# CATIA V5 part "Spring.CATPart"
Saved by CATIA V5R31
Part number: Part1
Bounding box of the stored display mesh (mm): x -50 to 50, y -44.999 to 44.983, z -4.984 to 154.984
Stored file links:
  D:\PROJECTS\Project 2021\US EDITION\CATIA V5 6R 2021\Resources\Tutorial Files\c19_catia_v5_6r2021_tut\C19_tut_01.CATPart\Spring.CATPart
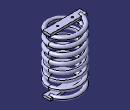
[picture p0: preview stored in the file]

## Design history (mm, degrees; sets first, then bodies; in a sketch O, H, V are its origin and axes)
Body1 (main body)
  Point1: (0, 0, 0)
  Point2: (0, 0, 150)
  Line1: type PtPt, FirstPoint Point2, SecondPoint Point1
  Point3: (40, 0, 0)
  Helix1: Direction Line1, RefPoint Point3, Pitch 20, Height 150, TaperAngle 0, Revolutions 1
  Plane1: type Normal, Curve Helix1, RefPoint vertex of Helix1, Ratio 0
  Sketch1 on Plane1, origin (0, -11.8615, 0.9439), H (1, 0, 0), V (0, 0.0793, 0.9968)
    circle A1 centre (-40, 149.5273) radius 5
    point P1 (-40, 149.5273)
    reference projected point E1 (-40, 149.5273) from vertex of Helix1
    radius A1 = 5
    coincidence: P1 E1
  Rib1: profile Sketch1, centre curve Helix1
  Sketch2 on xy-plane, origin (0, 0, 0), H (1, 0, 0), V (0, 1, 0)
    line L1 (-50, 10) -> (50, 10)
    line L2 (50, 10) -> (50, -10)
    line L3 (50, -10) -> (-50, -10)
    line L4 (-50, -10) -> (-50, 10)
    length L1 = 100
    distance L1 L3 = 20
    horizontal: L1 H, L3 H
    vertical: L2 V, L4 V
    symmetry: L3 L1 H, L2 L4 V
  Pad1: profile Sketch2, direction (0, 0, 1), length 3, mirrored extent
  Sketch3 on start face of Pad1, origin (0, 0, -3), H (1, 0, 0), V (0, -1, 0)
    circle A1 centre (-24.223, 0) radius 2.5
    point P1 (-24.223, 0)
    circle A2 centre (24.223, 0) radius 2.5
    point P2 (24.223, 0)
    radius A2 = 2.5
    coincidence: P1 H, P2 H
    symmetry: A2 A1 V
  Pocket1: profile Sketch3, direction (0, 0, 1), length 3
  Plane2: type Offset, RefPlane xy-plane, Offset 150
  Sketch4 on Plane2, origin (0, 0, 150), H (1, 0, 0), V (0, 1, 0)
    line L1 (-50, 10) -> (50, 10)
    line L2 (50, 10) -> (50, -10)
    line L3 (50, -10) -> (-50, -10)
    line L4 (-50, -10) -> (-50, 10)
    reference projected line E1 (50, -10) -> (50, 10) from edge [face of Pad1 from Sketch2.L2 | end face of Pad1]
    reference projected line E2 (-50, 10) -> (-50, -10) from edge [face of Pad1 from Sketch2.L4 | end face of Pad1]
    reference projected line E3 (-50, -10) -> (50, -10) from edge [face of Pad1 from Sketch2.L3 | end face of Pad1]
    reference projected line E4 (50, 10) -> (-50, 10) from edge [face of Pad1 from Sketch2.L1 | end face of Pad1]
    horizontal: L1 H, L3 H
    vertical: L2 V, L4 V
    coincidence: L2 E1, L4 E2, E3 L3, L1 E4
  Pad2: profile Sketch4, direction (0, 0, 1), length 3, mirrored extent
  Sketch5 on end face of Pad2, origin (0, 0, 153), H (1, 0, 0), V (0, 1, 0)
    circle A1 centre (-20.0406, 0) radius 2.5674
    point P1 (-20.0406, 0)
    circle A2 centre (20.0406, 0) radius 2.5674
    coincidence: P1 H
    symmetry: A1 A2 V
  Pocket2: profile Sketch5, direction (0, 0, -1), through (limit type 6)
